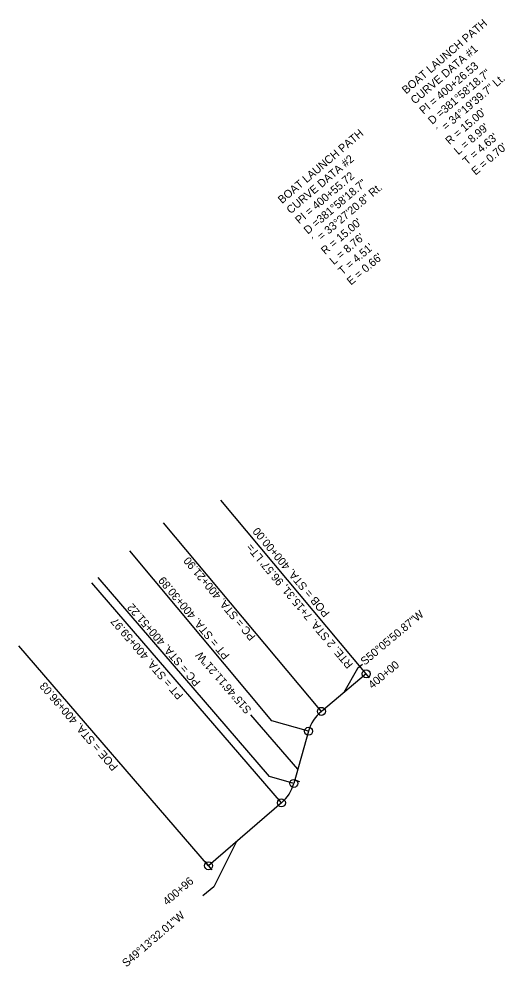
# Model space of a CAD drawing. Extents: x 939487 to 939669, y 627833 to 628188.
import ezdxf

# ---------------------------------------------------------------- set-up
doc = ezdxf.new("R2010")
doc.units = 0
for name, color, linetype in [('D_Roadway_Centerline', 7, 'Continuous'), ('D_Roadway_Centerline_Bearings', 7, 'Continuous'), ('D_Roadway_Centerline_CurveData', 7, 'Continuous'), ('D_Roadway_Centerline_Flags', 7, 'Continuous'), ('D_Roadway_Centerline_Text', 7, 'Continuous')]:
    doc.layers.add(name, color=color, linetype=linetype)

msp = doc.modelspace()

# ---------------------------------------------------------------- linework, layer by layer
at = {"layer": 'D_Roadway_Centerline'}
for p, q in [((939617.31, 627942.76), (939600.51, 627928.72)), ((939617.31, 627942.76), (939600.51, 627928.72)), ((939595.69, 627921.29), (939590.17, 627901.72)), ((939595.69, 627921.29), (939590.17, 627901.72)), ((939585.53, 627894.44), (939558.23, 627870.89)), ((939585.53, 627894.44), (939558.23, 627870.89))]:
    msp.add_line(p, q, dxfattribs=at)
for centre, start, end in [((939610.13, 627917.21), 129.9025, 164.2302), ((939610.13, 627917.21), 129.9025, 164.2302), ((939575.73, 627905.8), 310.7744, 344.2302), ((939575.73, 627905.8), 310.7744, 344.2302)]:
    msp.add_arc(centre, 15, start, end, dxfattribs=at)
at = {"layer": 'D_Roadway_Centerline_Flags'}
for p, q in [((939614.09, 627944.75), (939608.91, 627935.74)), ((939615.93, 627946.28), (939614.09, 627944.75)), ((939568.75, 627879.96), (939560.25, 627863.03)), ((939560.25, 627863.03), (939556.13, 627859.57))]:
    msp.add_line(p, q, dxfattribs=at)
for points in [[(939617.31, 627942.76), (939562.89, 628007.84)], [(939600.51, 627928.72), (939541.41, 627999.39)], [(939581.95, 627925.17), (939528.74, 627988.8)], [(939581.1, 627904.28), (939516.81, 627978.82)], [(939585.53, 627894.44), (939514.49, 627976.82)], [(939558.23, 627870.89), (939487.19, 627953.27)], [(939591.66, 627907.01), (939574.02, 627927.46)], [(939595.69, 627921.29), (939581.95, 627925.17)], [(939590.17, 627901.72), (939581.1, 627904.28)]]:
    msp.add_lwpolyline(points, dxfattribs=at)
for centre in [(939617.31, 627942.76), (939600.51, 627928.72), (939595.69, 627921.29), (939590.17, 627901.72), (939585.53, 627894.44), (939558.23, 627870.89)]:
    msp.add_circle(centre, 1.5, dxfattribs=at)
at = {"layer": 'D_Roadway_Centerline_Text'}
for points in [[(939618.59, 627941.23), (939616.02, 627944.3)], [(939592.42, 627902.35), (939590.5, 627902.89)], [(939559.54, 627869.38), (939556.92, 627872.41)], [(939559.54, 627869.38), (939556.92, 627872.41)]]:
    msp.add_lwpolyline(points, dxfattribs=at)

# ---------------------------------------------------------------- texts
at = {"layer": 'D_Roadway_Centerline_Bearings'}
for s, rotation, p in [('S50%%d05\'50.87"W', 40.0369, (939616.77, 627945.8)), ('S15%%d46\'11.21"W', 130.8991, (939574.52, 627929.37)), ('S49%%d13\'32.01"W', 40.7744, (939527.41, 627832.73))]:
    msp.add_text(s, height=3, rotation=rotation, dxfattribs=at).set_placement(p)
at = {"layer": 'D_Roadway_Centerline_CurveData'}
for s, rotation, p in [('BOAT LAUNCH PATH', 40.5492, (939632.28, 628159.84)), ('CURVE DATA #1', 40.5492, (939635.53, 628156.04)), ('PI = 400+26.53', 40.5492, (939638.79, 628152.24)), ('D =381%%d58\'18.7"', 40.5492, (939642.04, 628148.44)), ('´ = 34%%d19\'39.7" Lt.', 40.5492, (939645.29, 628144.64)), ("R = 15.00'", 40.5492, (939648.54, 628140.84)), ("L = 8.99'", 40.5492, (939651.79, 628137.04)), ('BOAT LAUNCH PATH', 40.2344, (939585.77, 628118.76)), ("T = 4.63'", 40.5492, (939655.04, 628133.24)), ("E = 0.70'", 40.5492, (939658.29, 628129.44)), ('CURVE DATA #2', 40.2344, (939589, 628114.94)), ('PI = 400+55.72', 40.2344, (939592.23, 628111.12)), ('D =381%%d58\'18.7"', 40.2344, (939595.46, 628107.31)), ('´ = 33%%d27\'20.8" Rt.', 40.2344, (939598.69, 628103.49)), ("R = 15.00'", 40.2344, (939601.92, 628099.67)), ("L = 8.76'", 40.2344, (939605.15, 628095.86)), ("T = 4.51'", 40.2344, (939608.38, 628092.04)), ("E = 0.66'", 40.2344, (939611.6, 628088.22))]:
    msp.add_text(s, height=3, rotation=rotation, dxfattribs=at).set_placement(p)
at = {"layer": 'D_Roadway_Centerline_Flags'}
for s, rotation, p in [('POB = STA. 400+00.00', 129.9025, (939603.83, 627965.59)), ("RTE. 2 STA. 7+15.31, 96.57' LT=", 129.9025, (939612.55, 627946.32)), ('PC = STA. 400+21.90', 129.9025, (939576.07, 627956.8)), ('PT = STA. 400+30.89', 129.8084, (939566.31, 627949.72)), ('PC = STA. 400+51.22', 130.7744, (939555.4, 627939.7)), ('PT = STA. 400+59.97', 130.7744, (939548.93, 627934.76)), ('POE = STA. 400+96.03', 130.7744, (939524.47, 627908.05))]:
    msp.add_text(s, height=3, rotation=rotation, dxfattribs=at).set_placement(p)
at = {"layer": 'D_Roadway_Centerline_Text'}
for s, rotation, p in [('400+00', 39.9025, (939619.61, 627936.99)), ('400+96', 40.7744, (939542.68, 627855.85))]:
    msp.add_text(s, height=3, rotation=rotation, dxfattribs=at).set_placement(p)

doc.saveas('drawing.dxf')
